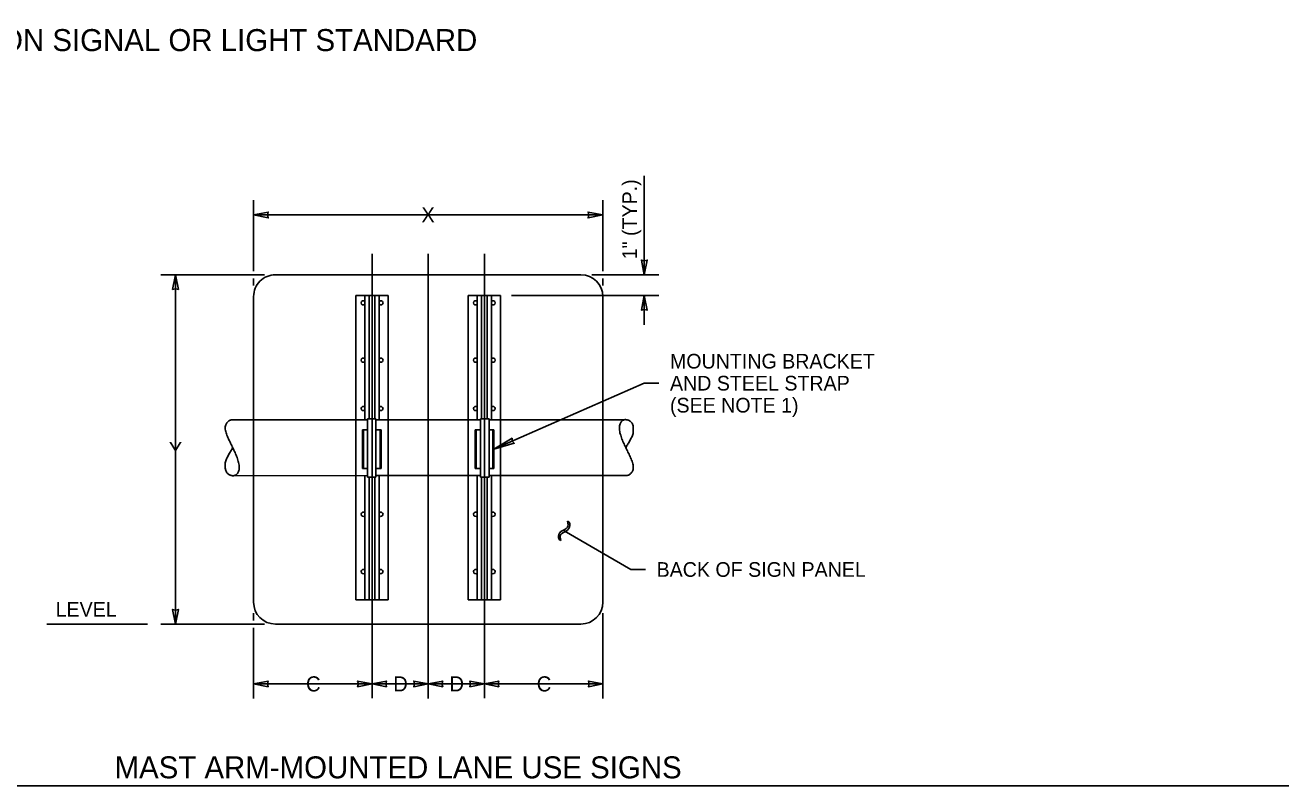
# Model space of a CAD drawing. Extents: x 99862 to 104211, y 98939 to 105076.
# Drawn here: x 101066 to 102436, y 103000 to 103829 of the extents above; entities that cross this region are included whole.
import ezdxf

# ---------------------------------------------------------------- set-up
doc = ezdxf.new("R2010")
doc.units = 0
for name, color, linetype in [('Level 1', 7, 'Continuous'), ('Level 15', 7, 'Continuous'), ('Level 19', 7, 'Continuous'), ('Level 2', 7, 'Continuous'), ('Level 20', 7, 'Continuous'), ('Level 3', 7, 'Continuous'), ('Level 6', 7, 'Continuous'), ('Level 7', 7, 'Continuous')]:
    doc.layers.add(name, color=color, linetype=linetype)

# ---------------------------------------------------------------- blocks, each defined once
blk = doc.blocks.new('T')
at = {"layer": 'Level 15'}
blk.add_lwpolyline([(0, 0), (-22.829, 2.985), (-21.773, 0), (-22.83, -2.985)], close=True, dxfattribs=at)

msp = doc.modelspace()

# ---------------------------------------------------------------- linework, layer by layer
at = {"layer": 'Level 1'}
for p, q in [((101339.4, 103557), (101339.4, 103557)), ((101339.4, 103557), (101672.8, 103557)), ((101315.6, 103398.8), (101315.6, 103533.2)), ((101315.6, 103533.2), (101315.6, 103533.2)), ((101696.6, 103533.2), (101696.6, 103533.2)), ((101696.6, 103533.2), (101696.6, 103398.8)), ((101315.6, 103398.8), (101315.6, 103337.9)), ((101696.6, 103398.8), (101696.6, 103337.9)), ((101315.6, 103337.9), (101315.6, 103199.8)), ((101696.6, 103199.8), (101696.6, 103337.9)), ((101339.4, 103176), (101672.8, 103176))]:
    msp.add_line(p, q, dxfattribs=at)
msp.add_lwpolyline([(99862, 102999.5), (103151, 102999.5), (103151, 105075.5), (99862, 105075.5)], close=True, dxfattribs=at)
for centre, start, end in [((101339.4, 103533.2), 89.9963, 179.9997), ((101672.8, 103533.2), 359.9994, 89.9948), ((101339.4, 103199.8), 179.9966, 269.9936), ((101672.8, 103199.8), 270, 359.9996)]:
    msp.add_arc(centre, 23.8, start, end, dxfattribs=at)
at = {"layer": 'Level 15'}
for p, q in [((101741.9, 103664.7), (101741.9, 103557)), ((101315.6, 103561), (101315.6, 103638.2)), ((101696.6, 103561), (101696.6, 103638.2)), ((101315.3, 103622.2), (101696.6, 103622.2)), ((101444.9, 103095.2), (101444.8, 103579.8)), ((101506.1, 103094.7), (101506.1, 103579.8)), ((101567.4, 103095.2), (101567.4, 103579.8)), ((101327.4, 103557), (101214.4, 103557)), ((101230.4, 103557), (101230.4, 103176)), ((101315.6, 103545.2), (101315.6, 103553)), ((101684.8, 103557), (101757.9, 103557)), ((101696.6, 103545.2), (101696.6, 103553)), ((101597, 103534.5), (101757.9, 103534.5)), ((101741.9, 103502.5), (101741.9, 103534.5)), ((101577.8, 103366.8), (101741.9, 103438.7)), ((101757.9, 103438.7), (101741.9, 103438.7)), ((101658.6, 103285.9), (101658.1, 103288.2)), ((101658.1, 103288.2), (101659.8, 103287.1)), ((101658.8, 103284.2), (101658.6, 103285.9)), ((101658.6, 103282.8), (101658.8, 103284.2)), ((101659.8, 103287.1), (101660.5, 103285.2)), ((101660.6, 103283.4), (101660.3, 103281.7)), ((101660.5, 103285.2), (101660.6, 103283.4)), ((101648.2, 103272), (101648.5, 103273.6)), ((101648.3, 103270.3), (101648.2, 103272)), ((101648.9, 103268.2), (101648.3, 103270.3)), ((101648.5, 103273.6), (101649.2, 103275.1)), ((101649.2, 103275.1), (101650.9, 103276.9)), ((101650.2, 103272.3), (101650, 103270.6)), ((101650, 103270.6), (101650.7, 103267)), ((101650.7, 103273.6), (101650.2, 103272.3)), ((101651.8, 103274.7), (101650.7, 103273.6)), ((101650.9, 103276.9), (101654.4, 103278.9)), ((101653.8, 103275.9), (101651.8, 103274.7)), ((101657.6, 103278.2), (101653.8, 103275.9)), ((101654.4, 103278.9), (101656.6, 103280.3)), ((101654.4, 103277.6), (101727.3, 103235.5)), ((101656.6, 103280.3), (101658, 103281.6)), ((101659.5, 103280.1), (101657.6, 103278.2)), ((101658, 103281.6), (101658.6, 103282.8)), ((101660.3, 103281.7), (101659.5, 103280.1)), ((101650.7, 103267), (101648.9, 103268.2)), ((101727.3, 103235.5), (101743.3, 103235.5)), ((101315.6, 103187.8), (101315.6, 103180)), ((101696.6, 103187.8), (101696.6, 103094.7)), ((101199.9, 103176), (101089.9, 103176)), ((101327.4, 103176), (101214.4, 103176)), ((101315.6, 103172), (101315.6, 103094.7)), ((101315.6, 103110.7), (101444.9, 103110.7)), ((101444.9, 103110.7), (101506.1, 103110.7)), ((101506.1, 103110.7), (101567.4, 103110.7)), ((101567.4, 103110.7), (101696.6, 103110.7))]:
    msp.add_line(p, q, dxfattribs=at)
for points in [[(101577.8, 103366.8), (101600, 103373.2), (101597.8, 103375.5), (101597.6, 103378.7)], [(101315.6, 103110.7), (101331.4, 103107.7), (101330.6, 103110.7), (101331.4, 103113.8)], [(101444.9, 103110.7), (101429.1, 103107.7), (101429.9, 103110.7), (101429.1, 103113.8)], [(101444.9, 103110.7), (101460.6, 103107.7), (101459.9, 103110.7), (101460.6, 103113.8)], [(101506.1, 103110.7), (101490.4, 103107.7), (101491.1, 103110.7), (101490.4, 103113.8)], [(101506.1, 103110.7), (101521.9, 103107.7), (101521.1, 103110.7), (101521.9, 103113.8)], [(101567.4, 103110.7), (101551.7, 103107.7), (101552.4, 103110.7), (101551.7, 103113.8)], [(101567.4, 103110.7), (101583.1, 103107.7), (101582.4, 103110.7), (101583.1, 103113.8)], [(101696.6, 103110.7), (101680.9, 103107.7), (101681.6, 103110.7), (101680.9, 103113.8)]]:
    msp.add_lwpolyline(points, close=True, dxfattribs=at)
at = {"layer": 'Level 19'}
for p, q in [((101292.9, 103398.8), (101439.7, 103398.8)), ((101563.1, 103398.8), (101449.1, 103398.8)), ((101719.4, 103398.8), (101572.5, 103398.8)), ((101439.7, 103337.9), (101293.6, 103337.8)), ((101563.1, 103337.9), (101449.1, 103337.9)), ((101721.7, 103337.9), (101572.5, 103337.9))]:
    msp.add_line(p, q, dxfattribs=at)
for points in [[(101292.9, 103398.8), (101292.7, 103398.8), (101292.1, 103398.8), (101291.1, 103398.7), (101289.9, 103398.3), (101288.7, 103397.6), (101287.6, 103396.8), (101286.5, 103395.6), (101285.5, 103394.2), (101284.8, 103392.3), (101284.6, 103390.8), (101284.6, 103389.9)], [(101729.9, 103386.1), (101729.9, 103390.9), (101729.7, 103392.4), (101729, 103394.2), (101728.1, 103395.7), (101727, 103396.9), (101725.8, 103397.7), (101724.7, 103398.3), (101723.4, 103398.7), (101722.2, 103398.9), (101720.7, 103399), (101719.8, 103398.7), (101718.7, 103398.3), (101717.6, 103397.5), (101716.6, 103396.5), (101715.7, 103395.2), (101715.1, 103393.4), (101714.7, 103391.3), (101714.7, 103388.8), (101715, 103386.1), (101715.7, 103383.3), (101716.5, 103380.5), (101717.5, 103377.7), (101718.6, 103375.1), (101719.8, 103372.5), (101721, 103369.9), (101722.2, 103367.4), (101723.4, 103364.8), (101724.6, 103362.4), (101725.8, 103359.9), (101727, 103357.3), (101728.1, 103354.8), (101729, 103352.2), (101729.7, 103349.5), (101729.9, 103347.8), (101729.9, 103346.9)], [(101284.6, 103350.7), (101284.6, 103345.9), (101284.8, 103344.4), (101285.6, 103342.5), (101286.5, 103341), (101287.6, 103339.9), (101288.7, 103339), (101289.9, 103338.4), (101291.1, 103338), (101292.4, 103337.8), (101293.9, 103337.8), (101294.8, 103338), (101295.9, 103338.5), (101297, 103339.2), (101298, 103340.2), (101298.9, 103341.5), (101299.5, 103343.3), (101299.9, 103345.4), (101299.9, 103347.9), (101299.5, 103350.7), (101298.9, 103353.4), (101298, 103356.2), (101297, 103359), (101295.9, 103361.7), (101294.8, 103364.3), (101293.6, 103366.8), (101292.4, 103369.4), (101291.1, 103371.9), (101289.9, 103374.4), (101288.7, 103376.9), (101287.6, 103379.4), (101286.5, 103382), (101285.6, 103384.6), (101284.8, 103387.2), (101284.6, 103389), (101284.6, 103389.8)], [(101729.9, 103386.1), (101729.9, 103385.4), (101729.7, 103383.9), (101729, 103381.7), (101728.1, 103379.6), (101727, 103377.6), (101725.8, 103375.5), (101724.7, 103373.4), (101723.4, 103371.4), (101722.4, 103369.7), (101721.8, 103368.7), (101721.7, 103368.5)], [(101284.6, 103350.7), (101284.6, 103351.4), (101284.8, 103352.8), (101285.6, 103355), (101286.5, 103357.1), (101287.6, 103359.2), (101288.7, 103361.3), (101289.9, 103363.3), (101291.1, 103365.3), (101292.1, 103367), (101292.7, 103368), (101292.9, 103368.3)], [(101721.7, 103337.9), (101721.8, 103337.9), (101722.4, 103337.9), (101723.4, 103338.1), (101724.6, 103338.5), (101725.8, 103339.1), (101727, 103340), (101728.1, 103341.1), (101729, 103342.6), (101729.7, 103344.5), (101729.9, 103346), (101729.9, 103346.8)]]:
    msp.add_open_spline(points, degree=3, dxfattribs=at)
at = {"layer": 'Level 2'}
for p, q in [((101427.3, 103534.5), (101462.4, 103534.5)), ((101427.3, 103534.5), (101427.3, 103398.8)), ((101437, 103534.5), (101437, 103398.8)), ((101441.7, 103534.5), (101441.7, 103399.7)), ((101448, 103534.5), (101448, 103399.7)), ((101452.7, 103534.5), (101452.7, 103398.8)), ((101462.4, 103534.5), (101462.4, 103398.8)), ((101585, 103534.5), (101549.8, 103534.5)), ((101549.8, 103534.5), (101549.8, 103398.8)), ((101559.6, 103534.5), (101559.6, 103398.8)), ((101564.3, 103534.5), (101564.3, 103399.7)), ((101570.5, 103534.5), (101570.5, 103399.7)), ((101575.2, 103534.5), (101575.2, 103398.8)), ((101585, 103534.5), (101585, 103398.8)), ((101427.3, 103398.8), (101427.3, 103337.9)), ((101462.4, 103398.8), (101462.4, 103337.9)), ((101549.8, 103398.8), (101549.8, 103337.9)), ((101585, 103398.8), (101585, 103337.9)), ((101427.3, 103337.9), (101427.3, 103202.3)), ((101437, 103337.9), (101437, 103202.3)), ((101441.7, 103336.3), (101441.7, 103202.3)), ((101448, 103336.3), (101448, 103202.3)), ((101452.7, 103337.9), (101452.7, 103202.3)), ((101462.4, 103337.9), (101462.4, 103202.3)), ((101549.8, 103337.9), (101549.8, 103202.3)), ((101559.6, 103337.9), (101559.6, 103202.3)), ((101564.3, 103336.3), (101564.3, 103202.3)), ((101570.5, 103336.3), (101570.5, 103202.3)), ((101575.2, 103337.9), (101575.2, 103202.3)), ((101585, 103337.9), (101585, 103202.3)), ((101427.3, 103202.3), (101462.4, 103202.3)), ((101585, 103202.3), (101549.8, 103202.3))]:
    msp.add_line(p, q, dxfattribs=at)
at = {"layer": 'Level 3'}
for p, q in [((101435.5, 103387.9), (101434.4, 103387.9)), ((101434.4, 103387.9), (101434.4, 103345.7)), ((101435.5, 103387.9), (101435.5, 103345.7)), ((101439.7, 103387.9), (101435.5, 103387.9)), ((101453.6, 103387.9), (101449.1, 103387.9)), ((101453.6, 103387.9), (101454.7, 103387.9)), ((101453.6, 103387.9), (101453.6, 103345.7)), ((101454.7, 103387.9), (101454.7, 103345.7)), ((101558.6, 103387.9), (101557.5, 103387.9)), ((101557.5, 103387.9), (101557.5, 103345.7)), ((101558.6, 103387.9), (101558.6, 103345.7)), ((101558.6, 103387.9), (101563.1, 103387.9)), ((101572.5, 103387.9), (101576.8, 103387.9)), ((101576.8, 103387.9), (101577.8, 103387.9)), ((101576.8, 103387.9), (101576.8, 103345.7)), ((101577.8, 103387.9), (101577.8, 103345.7)), ((101435.5, 103345.7), (101434.4, 103345.7)), ((101439.7, 103345.7), (101434.4, 103345.7)), ((101453.6, 103345.7), (101449.1, 103345.7)), ((101453.6, 103345.7), (101454.7, 103345.7)), ((101558.6, 103345.7), (101557.5, 103345.7)), ((101558.6, 103345.7), (101563.1, 103345.7)), ((101572.5, 103345.7), (101576.8, 103345.7)), ((101572.5, 103345.7), (101577.8, 103345.7)), ((101576.8, 103345.7), (101577.8, 103345.7))]:
    msp.add_line(p, q, dxfattribs=at)
at = {"layer": 'Level 6'}
for centre, start, end in [((101435.2, 103526.3), 39.9445, 180), ((101435.2, 103526.3), 180, 320.0555), ((101454.5, 103526.3), 0, 140.0555), ((101454.5, 103526.3), 219.9445, 0), ((101557.8, 103526.3), 39.9445, 180), ((101557.8, 103526.3), 180, 320.0555), ((101577, 103526.3), 0, 140.0555), ((101577, 103526.3), 219.9445, 0), ((101435.2, 103463.8), 39.9445, 180), ((101435.2, 103463.8), 180, 320.0555), ((101454.5, 103463.8), 0, 140.0555), ((101454.5, 103463.8), 219.9445, 0), ((101557.8, 103463.8), 39.9445, 180), ((101557.8, 103463.8), 180, 320.0555), ((101577, 103463.8), 0, 140.0555), ((101577, 103463.8), 219.9445, 0), ((101435.2, 103411), 39.9445, 180), ((101435.2, 103411), 180, 320.0555), ((101454.5, 103411), 360, 140.0555), ((101454.5, 103411), 219.9445, 0), ((101557.8, 103411), 39.9445, 180), ((101557.8, 103411), 180, 320.0555), ((101577, 103411), 360, 140.0555), ((101577, 103411), 219.9445, 0), ((101435.2, 103295.7), 39.9445, 180), ((101454.5, 103295.7), 360, 140.0555), ((101557.8, 103295.7), 39.9445, 180), ((101577, 103295.7), 360, 140.0555), ((101435.2, 103295.7), 180, 320.0555), ((101454.5, 103295.7), 219.9445, 0), ((101557.8, 103295.7), 180, 320.0555), ((101577, 103295.7), 219.9445, 0), ((101435.2, 103233.2), 39.9445, 180), ((101435.2, 103233.2), 180, 320.0555), ((101454.5, 103233.2), 360, 140.0555), ((101454.5, 103233.2), 219.9445, 0), ((101557.8, 103233.2), 39.9445, 180), ((101557.8, 103233.2), 180, 320.0555), ((101577, 103233.2), 360, 140.0555), ((101577, 103233.2), 219.9445, 0)]:
    msp.add_arc(centre, 2.34, start, end, dxfattribs=at)
at = {"layer": 'Level 7'}
for p, q in [((101439.7, 103336.3), (101439.7, 103399.7)), ((101439.7, 103399.7), (101449.1, 103399.7)), ((101449.1, 103399.7), (101449.1, 103336.3)), ((101563.1, 103336.3), (101563.1, 103399.7)), ((101563.1, 103399.7), (101572.5, 103399.7)), ((101572.5, 103399.7), (101572.5, 103336.3)), ((101449.1, 103336.3), (101439.7, 103336.3)), ((101572.5, 103336.3), (101563.1, 103336.3))]:
    msp.add_line(p, q, dxfattribs=at)

# ---------------------------------------------------------------- block references
at = {"layer": 'Level 15', "xscale": 0.700832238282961, "yscale": 1.0720268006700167}
for p, rotation in [((101315.6, 103622.2), 180), ((101741.9, 103557), -90), ((101230.4, 103557), 90), ((101741.9, 103534.5), 90), ((101230.4, 103176), -90)]:
    msp.add_blockref('T', p, dxfattribs=dict(at, rotation=rotation))
msp.add_blockref('T', (101696.6, 103622.2), dxfattribs=at)

# ---------------------------------------------------------------- texts
at = {"layer": 'Level 20'}
for s, height, p in [('SIGN INSTALLATION ON SIGNAL OR LIGHT STANDARD', 24, (100714.4, 103800.9)), ('X', 16.5, (101498.6, 103614)), ('MOUNTING BRACKET', 16, (101769.9, 103454.7)), ('AND STEEL STRAP', 16, (101769.9, 103430.7)), ('(SEE NOTE 1)', 16, (101769.9, 103406.7)), ('Y', 16.5, (101223, 103358.2)), ('LEVEL', 16, (101099.6, 103184)), ('C', 16.5, (101372.8, 103102.5)), ('D', 16.5, (101467.9, 103102.5)), ('D', 16.5, (101529.2, 103102.5)), ('C', 16.5, (101624.5, 103102.5)), ('MAST ARM-MOUNTED LANE USE SIGNS', 24, (101163.9, 103007.7))]:
    msp.add_text(s, height=height, dxfattribs=at).set_placement(p)
for s, rotation, p in [('1" (TYP.)', 90, (101733.9, 103573.8)), ('BACK OF SIGN PANEL', 360, (101755.3, 103227.5))]:
    msp.add_text(s, height=16, rotation=rotation, dxfattribs=at).set_placement(p)

doc.saveas('drawing.dxf')
